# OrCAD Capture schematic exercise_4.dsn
size A
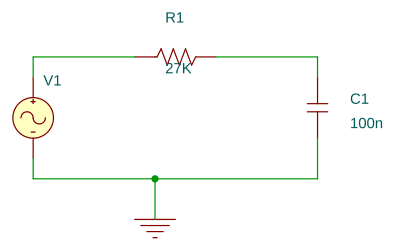
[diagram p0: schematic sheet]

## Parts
C1  100n  [cap196]
R1  27K  [AXRC05]
V1  VAC

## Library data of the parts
C1 = C
R1 = R
V1 = VAC

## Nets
0: C1.1 V1.2(-)
N00754: R1.1 V1.1(+)
N00767: C1.2 R1.2
